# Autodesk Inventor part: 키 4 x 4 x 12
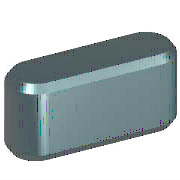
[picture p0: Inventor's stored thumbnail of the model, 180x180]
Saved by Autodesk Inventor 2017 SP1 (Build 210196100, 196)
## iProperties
IsCustomPart: 1
Created: 2012-02
Part Number: 키 4 x 4 x 12
Material: 강철, 연강
Description: 키 및 해당 키홈
Document SubType Name: Modeling
Standard: KS B 1311
Designer: mduedu
Standards Organization: KS
Language: ko-KR
Size Designation: 4 x 4 x 12
Categories: <MemberInstance><Categories><Category DisplayName="샤프트 부품" InternalName="7f7aeb1f-a693-4053-b835-cee3144e0d98" Mnemonic="SHFT"><Category DisplayName="키" Interna
Density: 7.86 g/cm^3
Mass: 1.38739 g
Surface Area: 1.94869 cm^2
Volume: 0.176513 cm^3
Appearance: 노란색
Author: mduedu
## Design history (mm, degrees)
workplane "Work Plane1"
workplane "Work Plane2"
sketch "스케치1"
  geometry: L1 (2, 2)-(10, 2); L2 (10, -2)-(2, -2); L3 (0, 9.4)-(0, -7.4) reference; L4 (-5, 0)-(30, 0) reference; L5 (12, 0)-(12, 7); A1 r 2 centre (2, 0) between (2, 2) and (2, -2); A2 r 2 centre (10, 0) between (10, -2) and (10, 2)
  constraints: 6 end point, 5 point on circle, 4 tangent, 3 point on line, 2 centre point, 1 horizontal, 1 parallel, 1 perpendicular
  dimensions: "d0" = 2 radius of A1 (= 0.5 x PB); "d13" = 2 radius of A2 (= 0.5 x PB); "d14" = 12 distance between parallel lines of L5 L3 (= NLG)
extrude "본체1" new body sketch "스케치1" taper "d3" = 0 deg; stored distance "d4" = 10
workplane "Work Plane3"
body "Solid1"
chamfer "모따기1" distance "d8" = 0.25 (= PHH); stored, may be unused: second distance "d9" = 0.25 (= PHH), angle "d15" = 45 deg
other parameters: "d1" = -2.5 (= -PNT), "d2" = 1.5 (= PH - PNT), "NLG" = 12 [user parameter; used in 3 equation terms], "PB" = 4 [user parameter; used in 2 equation terms], "PNT" = 2.5 [user parameter; used in 2 equation terms], "PH" = 4 [user parameter; used in 1 equation term], "PHH" = 0.25 [user parameter; used in 2 equation terms], "d10" = 0, "d16" = 0, "d17" = 0, "d18" = 0, "PLB2" = 12 (= NLG) [user parameter], "WDMAX" = 12 [user parameter], "PLB1" = 12 (= NLG) [user parameter], "RR" = 0.08 [user parameter], "PUEB" = 1.8 [user parameter]
